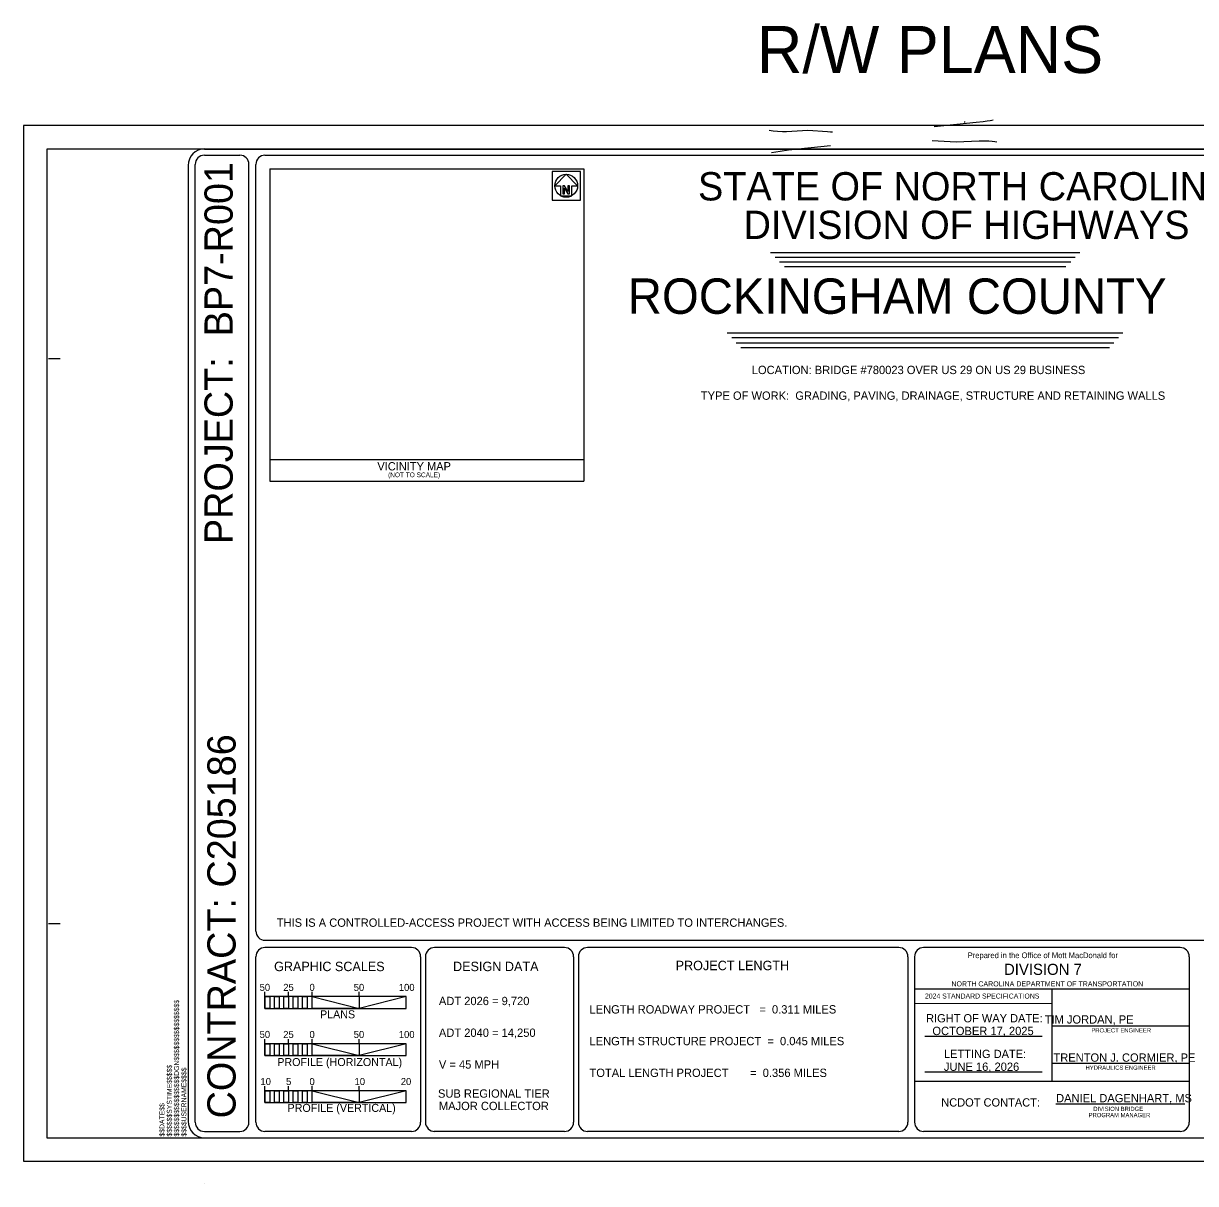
# Model space of a CAD drawing. Extents: x 2538775 to 2540754, y 826823 to 828055.
# Drawn here: x 2538775 to 2540020, y 826823 to 828055 of the extents above; entities that cross this region are included whole.
import ezdxf

# ---------------------------------------------------------------- set-up
doc = ezdxf.new("R2010")
doc.units = 0
for name, color, linetype in [('Old_Level_1', 7, 'Continuous'), ('Old_Level_10', 7, 'Continuous'), ('Old_Level_23', 7, 'Continuous'), ('Old_Level_38', 7, 'Continuous'), ('Old_Level_40', 7, 'Continuous'), ('Old_Level_41', 7, 'Continuous'), ('Old_Level_42', 7, 'Continuous'), ('Old_Level_62', 7, 'Continuous'), ('Old_Level_63', 7, 'Continuous'), ('Sheet Title CELL', 7, 'Continuous')]:
    doc.layers.add(name, color=color, linetype=linetype)

msp = doc.modelspace()

# ---------------------------------------------------------------- linework, layer by layer
at = {"layer": 'Old_Level_1'}
msp.add_line((2538967, 826823.1), (2538967, 826823.1), dxfattribs=at)
at = {"layer": 'Old_Level_10'}
for p, q in [((2539351.6, 827895.1), (2539339.6, 827882.8)), ((2539363.7, 827882.8), (2539351.6, 827895.1)), ((2539339.6, 827882.8), (2539345.6, 827882.8)), ((2539345.6, 827882.8), (2539345.6, 827872.2)), ((2539357.7, 827872.2), (2539357.7, 827882.8)), ((2539357.7, 827882.8), (2539363.7, 827882.8)), ((2539345.6, 827872.2), (2539357.7, 827872.2))]:
    msp.add_line(p, q, dxfattribs=at)
for points in [[(2539336.6, 827867.6), (2539366.7, 827867.6), (2539366.7, 827898.1), (2539336.6, 827898.1)], [(2539348, 827882.8), (2539348, 827874.2), (2539349.6, 827874.2), (2539349.6, 827880.2), (2539353.2, 827874.2), (2539354.9, 827874.2), (2539354.9, 827882.8), (2539353.2, 827882.8), (2539353.2, 827876.8), (2539349.6, 827882.8)]]:
    msp.add_lwpolyline(points, close=True, dxfattribs=at)
msp.add_ellipse((2539351.6, 827882.8), major_axis=(0, 12.2), ratio=0.985213, dxfattribs=at)
at = {"layer": 'Old_Level_23'}
for points in [[(2539742.5, 827945.6), (2539787.1, 827950.3), (2539794.4, 827951.1), (2539798.8, 827951.7), (2539802.1, 827952.3), (2539803.7, 827952.6), (2539805.1, 827953)], [(2539775.5, 827950.4), (2539774.3, 827950.2)], [(2539567.2, 827941.7), (2539571.3, 827941.3), (2539575.9, 827940.9), (2539581.2, 827940.6), (2539585.7, 827940.6), (2539608.3, 827941.7), (2539629.3, 827940.4), (2539632.2, 827940.2), (2539634.6, 827940.2)], [(2539632.4, 827925.3), (2539587.8, 827920.6), (2539578.7, 827919.3), (2539574.2, 827918.5), (2539569.5, 827917.7)], [(2539809, 827929.2), (2539806.8, 827929.6), (2539804, 827929.9), (2539800.7, 827930.1), (2539796.8, 827930.3), (2539790.4, 827930.3), (2539765.7, 827929.2), (2539740.3, 827930.7)]]:
    msp.add_lwpolyline(points, dxfattribs=at)
at = {"layer": 'Old_Level_40'}
for p, q in [((2538957.4, 827398.3), (2538957.4, 827905.4)), ((2539014.5, 827398.1), (2539014.5, 827905.4)), ((2539021.8, 827398.1), (2539021.8, 827905.4)), ((2539036.8, 827900.9), (2539370.3, 827900.9)), ((2539036.8, 827900.9), (2539036.8, 827569.2)), ((2539370.3, 827900.9), (2539370.3, 827569.2)), ((2539568.6, 827811.9), (2539897.3, 827811.9)), ((2539573.4, 827807), (2539892.4, 827807)), ((2539578.2, 827802.1), (2539887.6, 827802.1)), ((2539583.5, 827797.2), (2539882.2, 827797.2)), ((2539522.5, 827726.5), (2539943.1, 827726.5)), ((2539527.4, 827721.6), (2539938.3, 827721.6)), ((2539532.2, 827716.1), (2539933.4, 827716.1)), ((2539537.1, 827711.2), (2539928.6, 827711.2)), ((2539036.8, 827592), (2539370.3, 827592)), ((2539036.8, 827569.2), (2539370.3, 827569.2)), ((2538957.4, 826888.3), (2538957.4, 827398.3)), ((2539014.5, 826888.3), (2539014.5, 827398.1)), ((2539021.8, 827091.3), (2539021.8, 827398.1)), ((2540433.1, 827081.4), (2539031.5, 827081.4)), ((2539021.8, 826888.3), (2539021.8, 827064)), ((2539187.2, 827073.8), (2539031.5, 827073.8)), ((2539196.8, 827064), (2539196.8, 826888.3)), ((2539202, 827064), (2539202, 826888.3)), ((2539349.7, 827073.8), (2539211.7, 827073.8)), ((2539359.3, 827064), (2539359.3, 826888.3)), ((2539364.6, 827064), (2539364.6, 826888.3)), ((2539704.9, 827073.8), (2539374.2, 827073.8)), ((2539714.5, 827064), (2539714.5, 826888.3)), ((2539721.7, 827064), (2539721.7, 826888.3)), ((2540003.8, 827073.8), (2539731.4, 827073.8)), ((2540013.5, 827064), (2540013.5, 826888.3)), ((2539031.5, 827021.6), (2539031.5, 827026.6)), ((2539031.5, 827026.6), (2539031.5, 827026.6)), ((2539056.5, 827021.6), (2539056.5, 827026.6)), ((2539081.5, 827021.6), (2539081.5, 827026.6)), ((2539131.5, 827021.6), (2539131.5, 827026.6)), ((2539721.6, 827029.9), (2540013.5, 827029.9)), ((2539867.6, 827029.8), (2539867.6, 826932)), ((2539031.5, 827021.6), (2539031.5, 827009.1)), ((2539031.5, 827021.6), (2539031.5, 827021.6)), ((2539181.5, 827021.6), (2539031.5, 827021.6)), ((2539066.5, 827021.6), (2539066.5, 827009.1)), ((2539131.5, 827021.6), (2539131.5, 827009.1)), ((2539721.6, 827014.7), (2539867.5, 827014.5)), ((2539031.5, 827009.1), (2539181.5, 827009.1)), ((2539031.5, 826971.6), (2539031.5, 826976.6)), ((2539031.5, 826971.6), (2539031.5, 826976.6)), ((2539031.5, 826976.6), (2539031.5, 826976.6)), ((2539031.5, 826971.6), (2539031.5, 826959.1)), ((2539031.5, 826971.6), (2539031.5, 826971.6)), ((2539181.5, 826971.6), (2539031.5, 826971.6)), ((2539031.5, 826971.6), (2539031.5, 826971.6)), ((2539181.5, 826971.6), (2539031.5, 826971.6)), ((2539056.5, 826971.6), (2539056.5, 826976.6)), ((2539056.5, 826971.6), (2539056.5, 826976.6)), ((2539066.5, 826971.6), (2539066.5, 826959.1)), ((2539081.5, 826971.6), (2539081.5, 826976.6)), ((2539081.5, 826971.6), (2539081.5, 826976.6)), ((2539131.5, 826971.6), (2539131.5, 826976.6)), ((2539131.5, 826971.6), (2539131.5, 826976.6)), ((2539131.5, 826971.6), (2539131.5, 826959.1)), ((2539031.5, 826959.1), (2539181.5, 826959.1)), ((2539721.4, 826932), (2540013.5, 826932)), ((2539031.5, 826921.6), (2539031.5, 826926.6)), ((2539031.5, 826921.6), (2539031.5, 826926.6)), ((2539031.5, 826921.6), (2539031.5, 826926.6)), ((2539031.5, 826926.6), (2539031.5, 826926.6)), ((2539031.5, 826921.6), (2539031.5, 826909.1)), ((2539031.5, 826921.6), (2539031.5, 826921.6)), ((2539181.5, 826921.6), (2539031.5, 826921.6)), ((2539031.5, 826921.6), (2539031.5, 826921.6)), ((2539181.5, 826921.6), (2539031.5, 826921.6)), ((2539031.5, 826921.6), (2539031.5, 826921.6)), ((2539181.5, 826921.6), (2539031.5, 826921.6)), ((2539056.5, 826921.6), (2539056.5, 826926.6)), ((2539056.5, 826921.6), (2539056.5, 826926.6)), ((2539056.5, 826921.6), (2539056.5, 826926.6)), ((2539066.5, 826921.6), (2539066.5, 826909.1)), ((2539081.5, 826921.6), (2539081.5, 826926.6)), ((2539081.5, 826921.6), (2539081.5, 826926.6)), ((2539081.5, 826921.6), (2539081.5, 826926.6)), ((2539131.5, 826921.6), (2539131.5, 826926.6)), ((2539131.5, 826921.6), (2539131.5, 826926.6)), ((2539131.5, 826921.6), (2539131.5, 826926.6)), ((2539131.5, 826921.6), (2539131.5, 826909.1)), ((2539031.5, 826909.1), (2539181.5, 826909.1)), ((2539871.9, 826907.9), (2540008.8, 826907.9)), ((2538967.1, 826878.5), (2539004.8, 826878.5)), ((2539187.2, 826878.5), (2539031.5, 826878.5)), ((2539349.7, 826878.5), (2539210.8, 826878.5)), ((2539704.9, 826878.5), (2539374.2, 826878.5)), ((2540003.8, 826878.5), (2539731.3, 826878.5))]:
    msp.add_line(p, q, dxfattribs=at)
for points in [[(2538967.1, 827921.8), (2540432.7, 827921.8)], [(2538967.1, 827915.2), (2539004.8, 827915.2)], [(2539031.5, 827915.2), (2540433.1, 827915.2)], [(2538949.9, 827904.4), (2538949.9, 827398.3)], [(2538949.9, 827398.3), (2538949.9, 826889.3)], [(2538967.1, 826871.8), (2540432.7, 826871.8)]]:
    msp.add_lwpolyline(points, dxfattribs=at)
for points in [[(2539031.5, 827021.6), (2539036.5, 827021.6), (2539036.5, 827009.1), (2539031.5, 827009.1)], [(2539041.5, 827021.6), (2539046.5, 827021.6), (2539046.5, 827009.1), (2539041.5, 827009.1)], [(2539051.5, 827021.6), (2539056.5, 827021.6), (2539056.5, 827009.1), (2539051.5, 827009.1)], [(2539061.5, 827021.6), (2539066.5, 827021.6), (2539066.5, 827009.1), (2539061.5, 827009.1)], [(2539071.5, 827021.6), (2539076.5, 827021.6), (2539076.5, 827009.1), (2539071.5, 827009.1)], [(2539081.5, 827021.6), (2539131.5, 827009.1), (2539081.5, 827009.1)], [(2539181.5, 827021.6), (2539131.5, 827009.1), (2539181.5, 827009.1)], [(2539031.5, 826971.6), (2539036.5, 826971.6), (2539036.5, 826959.1), (2539031.5, 826959.1)], [(2539041.5, 826971.6), (2539046.5, 826971.6), (2539046.5, 826959.1), (2539041.5, 826959.1)], [(2539051.5, 826971.6), (2539056.5, 826971.6), (2539056.5, 826959.1), (2539051.5, 826959.1)], [(2539061.5, 826971.6), (2539066.5, 826971.6), (2539066.5, 826959.1), (2539061.5, 826959.1)], [(2539071.5, 826971.6), (2539076.5, 826971.6), (2539076.5, 826959.1), (2539071.5, 826959.1)], [(2539081.5, 826971.6), (2539131.5, 826959.1), (2539081.5, 826959.1)], [(2539181.5, 826971.6), (2539131.5, 826959.1), (2539181.5, 826959.1)], [(2539031.5, 826921.6), (2539036.5, 826921.6), (2539036.5, 826909.1), (2539031.5, 826909.1)], [(2539041.5, 826921.6), (2539046.5, 826921.6), (2539046.5, 826909.1), (2539041.5, 826909.1)], [(2539051.5, 826921.6), (2539056.5, 826921.6), (2539056.5, 826909.1), (2539051.5, 826909.1)], [(2539061.5, 826921.6), (2539066.5, 826921.6), (2539066.5, 826909.1), (2539061.5, 826909.1)], [(2539071.5, 826921.6), (2539076.5, 826921.6), (2539076.5, 826909.1), (2539071.5, 826909.1)], [(2539081.5, 826921.6), (2539131.5, 826909.1), (2539081.5, 826909.1)], [(2539181.5, 826921.6), (2539131.5, 826909.1), (2539181.5, 826909.1)]]:
    msp.add_lwpolyline(points, close=True, dxfattribs=at)
for centre, major_axis, start_param, end_param in [((2538967.1, 827904.4), (0, 17.5), 6.283183, 7.853978), ((2538967.1, 827905.4), (0, 9.81), 6.283183, 7.853978), ((2539004.8, 827905.4), (0, 9.81), 4.712408, 6.283194), ((2539031.5, 827905.4), (0, -9.81), 3.141603, 4.712391), ((2539031.5, 827091.3), (0, -9.81), 4.712389, 6.283185), ((2539031.5, 827064), (0, -9.81), 3.141593, 4.712389), ((2539031.5, 827064), (0, 9.81), 0, 1.570796), ((2539187.2, 827064), (0, 9.81), 4.712389, 6.283185), ((2539211.7, 827064), (0, -9.81), 3.141593, 4.712389), ((2539349.7, 827064), (0, 9.81), 4.712389, 6.283185), ((2539374.2, 827064), (0, -9.81), 3.140818, 4.712389), ((2539704.9, 827064), (0, 9.81), 4.711742, 6.282478), ((2539731.3, 827064), (0, 9.81), 6.282622, 7.852769), ((2540003.8, 827064), (0, 9.81), 4.712389, 6.282258), ((2538967.1, 826889.3), (0, -17.5), 4.712389, 6.283185), ((2538967.1, 826888.3), (0, -9.81), 4.712389, 6.283185), ((2539004.8, 826888.3), (0, 9.81), 3.141593, 4.712389), ((2539031.5, 826888.3), (0, -9.81), 4.712389, 6.283185), ((2539187.2, 826888.3), (0, -9.81), 0, 1.570796), ((2539211.7, 826888.3), (0, -9.81), 4.712389, 6.283185), ((2539349.7, 826888.3), (0, -9.81), 0, 1.570796), ((2539374.2, 826888.3), (0, -9.81), 4.712389, 6.283185), ((2539704.9, 826888.3), (0, -9.81), 6.283185, 7.853277), ((2539731.3, 826888.3), (0, 9.81), 1.569081, 3.141593), ((2540003.8, 826888.3), (0, 9.81), 3.141593, 4.712389)]:
    msp.add_ellipse(centre, major_axis=major_axis, ratio=0.985213, start_param=start_param, end_param=end_param, dxfattribs=at)
at = {"layer": 'Old_Level_41'}
for p, q in [((2538801.4, 827699.3), (2538813.9, 827699.3)), ((2538801.4, 827099.3), (2538813.9, 827099.3))]:
    msp.add_line(p, q, dxfattribs=at)
at = {"layer": 'Old_Level_62'}
msp.add_lwpolyline([(2538799.9, 826871.8), (2540449.9, 826871.8), (2540449.9, 827921.8), (2538799.9, 827921.8)], close=True, dxfattribs=at)
at = {"layer": 'Old_Level_63'}
msp.add_lwpolyline([(2538774.9, 826846.8), (2540474.9, 826846.8), (2540474.9, 827946.8), (2538774.9, 827946.8)], close=True, dxfattribs=at)
at = {"layer": 'Sheet Title CELL'}
for p, q in [((2539867.6, 826990.5), (2540013.5, 826990.5)), ((2539857.3, 826979.4), (2539732.6, 826979.4)), ((2539857.3, 826941.4), (2539732.6, 826941.4)), ((2539867.6, 826950.9), (2540013.5, 826950.8)), ((2539867.6, 826950.9), (2540013.5, 826950.8))]:
    msp.add_line(p, q, dxfattribs=at)

# ---------------------------------------------------------------- texts
at = {"layer": 'Old_Level_1'}
msp.add_text('R/W PLANS', height=50, rotation=360, dxfattribs=at).set_placement((2539554.2, 828002.5))
at = {"layer": 'Old_Level_38'}
for s, height, rotation, p in [('ROCKINGHAM COUNTY', 37.58, 360, (2539417, 827746.8)), ('      TIM JORDAN, PE      ', 8.83, 359.9851, (2539840.2, 826993)), ('OCTOBER 17, 2025', 8.83, 359.9851, (2539740.6, 826980.8)), ('JUNE 16, 2026', 8.83, 359.9851, (2539752.8, 826942.8)), ('TRENTON J. CORMIER, PE', 8.83, 359.9851, (2539869.2, 826952.5))]:
    msp.add_text(s, height=height, rotation=rotation, dxfattribs=at).set_placement(p)
at = {"layer": 'Old_Level_40'}
for s, height, rotation, p in [('PROJECT:  BP7-R001', 30, 90, (2538997.2, 827502.3)), ('STATE OF NORTH CAROLINA', 30.077, 360, (2539491.6, 827867.2)), ('DIVISION OF HIGHWAYS', 30.077, 360, (2539540, 827826.3)), ('(NOT TO SCALE)', 5.005, 360, (2539162.3, 827573.3)), ('CONTRACT: C205186', 30, 90, (2539000.3, 826892.3)), ('THIS IS A CONTROLLED-ACCESS PROJECT WITH ACCESS BEING LIMITED TO INTERCHANGES.', 8.83, 360, (2539044, 827095.8)), ('Prepared in the Office of Mott MacDonald for', 6.014, 360, (2539778.1, 827062.5)), ('GRAPHIC SCALES', 10, 360, (2539041.2, 827048.7)), ('DESIGN DATA', 10.023, 360, (2539231.3, 827048.7)), ('PROJECT LENGTH', 10.023, 360, (2539467.8, 827049.7)), ('DIVISION 7', 11.83, 360, (2539816.7, 827044.7)), ('50', 7.5, 360, (2539025.8, 827027.7)), ('25', 7.5, 360, (2539050.9, 827027.7)), ('0', 7.5, 360, (2539078.8, 827027.7)), ('50', 7.5, 360, (2539125.8, 827027.7)), ('100', 7.5, 360, (2539173.7, 827027.7)), ('NORTH CAROLINA DEPARTMENT OF TRANSPORTATION', 5.412, 360, (2539760.8, 827032.5)), ('ADT 2026 = 9,720', 8.83, 360, (2539216.3, 827012.6)), ('2024 STANDARD SPECIFICATIONS', 5.299, 360, (2539732.7, 827019.6)), ('PLANS', 8.5, 360, (2539090, 826998.6)), ('LENGTH ROADWAY PROJECT   =  0.311 MILES ', 8.83, 360, (2539376.3, 827003.7)), ('RIGHT OF WAY DATE:', 8.769, 360, (2539733.9, 826994.3)), ('50', 7.5, 360, (2539025.8, 826977.7)), ('25', 7.5, 360, (2539050.9, 826977.7)), ('0', 7.5, 360, (2539078.8, 826977.7)), ('0', 7.5, 360, (2539078.8, 826977.6)), ('50', 7.5, 360, (2539125.8, 826977.7)), ('100', 7.5, 360, (2539173.7, 826977.7)), ('ADT 2040 = 14,250', 8.83, 360, (2539216.3, 826978.9)), ('LENGTH STRUCTURE PROJECT  =  0.045 MILES', 8.83, 360, (2539376.3, 826970)), ('LETTING DATE:', 8.769, 360, (2539752.9, 826956.4)), ('PROFILE (HORIZONTAL)', 8.5, 360, (2539044.6, 826947.9)), ('V = 45 MPH', 8.83, 360, (2539216.3, 826945.2)), ('TOTAL LENGTH PROJECT       =  0.356 MILES', 8.83, 360, (2539376.3, 826936.3)), ('10', 7.5, 360, (2539026.7, 826927.7)), ('5', 7.5, 360, (2539053.9, 826927.7)), ('0', 7.5, 360, (2539078.8, 826927.7)), ('0', 7.5, 360, (2539078.8, 826927.6)), ('0', 7.5, 360, (2539078.8, 826927.6)), ('10', 7.5, 360, (2539126.7, 826927.7)), ('20', 7.5, 360, (2539175.8, 826927.7)), ('SUB REGIONAL TIER', 8.83, 360, (2539215.3, 826914.3)), ('PROFILE (VERTICAL)', 8.5, 360, (2539055.5, 826899.2)), ('MAJOR COLLECTOR', 8.83, 360, (2539216.3, 826901.1)), ('NCDOT CONTACT:', 8.769, 360, (2539750, 826904.9)), (' DIVISION BRIDGE', 4.515, 360, (2539909.8, 826900.2)), ('PROGRAM MANAGER', 4.515, 360, (2539906.6, 826893.6))]:
    msp.add_text(s, height=height, rotation=rotation, dxfattribs=at).set_placement(p)
at = {"layer": 'Old_Level_41'}
for s, p in [('$$$$$$$$$$$$$$$$DGN$$$$$$$$$$$$$$$$', (2538940.2, 826873)), ('$$$$$$SYSTIME$$$$$', (2538932.5, 826873)), ('$$$$USERNAME$$$$', (2538948, 826873)), ('$$DATE$$', (2538924.7, 826873))]:
    msp.add_text(s, height=5.25, rotation=90, dxfattribs=at).set_placement(p)
at = {"layer": 'Old_Level_42'}
for s, height, p in [('LOCATION: BRIDGE #780023 OVER US 29 ON US 29 BUSINESS', 8.83, (2539548.7, 827682.8)), ('TYPE OF WORK:  GRADING, PAVING, DRAINAGE, STRUCTURE AND RETAINING WALLS', 8.83, (2539494.6, 827655.5)), ('VICINITY MAP', 8.769, (2539150.9, 827580.5)), ('DANIEL DAGENHART, MS', 8.83, (2539872, 826909.4))]:
    msp.add_text(s, height=height, rotation=360, dxfattribs=at).set_placement(p)
at = {"layer": 'Sheet Title CELL'}
for s, rotation, p in [('PROJECT ENGINEER', 360, (2539909.5, 826983.6)), ('HYDRAULICS ENGINEER', 359.9851, (2539903.3, 826943.9))]:
    msp.add_text(s, height=4.515, rotation=rotation, dxfattribs=at).set_placement(p)

doc.saveas('drawing.dxf')
